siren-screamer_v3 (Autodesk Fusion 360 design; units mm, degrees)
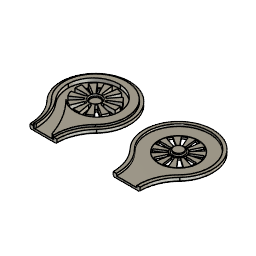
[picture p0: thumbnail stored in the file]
sketch "Skizze1" plane through (0, 0, 0) normal (0, 0, 1) x axis (1, 0, 0)
  line L1 (10, -50) -> (-10, -50)
  line L2 (8.969, -25.7617) -> (10, -50)
  line L3 (14.8492, -14.8492) -> (14.1421, -14.1421)
  line L4 (16.9905, -14.1421) -> (14.1421, -14.1421)
  line L5 (22, 0) -> (20, 0)
  line L6 (16.2635, 16.2635) -> (14.1421, 14.1421)
  line L7 (21.2962, 14.1421) -> (14.1421, 14.1421)
  line L8 (0, 24) -> (0, 20)
  line L9 (-17.6777, 17.6777) -> (-14.1421, 14.1421)
  line L10 (-26, 0) -> (-20, 0)
  line L11 (-19.0919, -19.0919) -> (-14.1421, -14.1421)
  line L12 (0, -10) -> (0, 0)
  line L13 (-21.2132, -21.2132) -> (-19.0919, -19.0919)
  line L14 (-10, -14.1421) -> (-14.1421, -14.1421)
  line L15 (-8, -46.3456) -> (-8, -50)
  circle C1 centre (0, 0) radius 20
  arc A1 centre (1.0544, 0.9401) radius 20.9666 clockwise from (22, 0) to (0, -20)
  arc A2 centre (-0.9455, 1.05) radius 22.9695 clockwise from (0, 24) to (22, 0)
  arc A3 centre (-1.0462, -0.95) radius 24.9719 clockwise from (-26, 0) to (0, 24)
  arc A4 centre (48.368, -48.368) radius 38.4027 clockwise from (10, -50) to (21.2132, -21.2132)
  arc A5 centre (-48.368, -48.368) radius 38.4027 clockwise from (-21.2132, -21.2132) to (-10, -50)
  arc A6 centre (-56.6095, -50) radius 48.6095 clockwise from (-19.0919, -19.0919) to (-8, -50)
  arc A7 centre (0, 0) radius 20 clockwise from (0, -20) to (-14.1421, -14.1421)
  arc A8 centre (4.2758, 0.1591) radius 30.2762 clockwise from (-19.0919, -19.0919) to (-26, 0)
  arc A9 centre (0, 0) radius 30 clockwise from (-21.2132, -21.2132) to (21.2132, -21.2132)
  arc A10 centre (-78.8875, -78.8875) radius 91.5638 clockwise from (-14.1421, -14.1421) to (8, -50)
  point P1 (0, 0)
  point P2 (0, 0)
  point P6 (0, -50)
  point P8 (0, -20)
  point P9 (14.1421, -14.1421)
  point P12 (20, 0)
  point P14 (14.1421, 14.1421)
  point P17 (0, 20)
  point P19 (-14.1421, 14.1421)
  point P21 (-20, 0)
  point P7 (0, 0)
  point P23 (-14.1421, -14.1421)
  point P10 (14.8492, -14.8492)
  point P25 (0, -20)
  point P15 (16.2635, 16.2635)
  point P20 (-17.6777, 17.6777)
  point P29 (0, -20)
  point P33 (0, 0)
  point P4 (10, -50)
  point P37 (-10, -50)
  point P31 (21.2132, -21.2132)
  point P36 (-21.2132, -21.2132)
  point P38 (-8, -50)
  point P40 (-21.2132, -21.2132)
  point P41 (0, 0)
  point P44 (8, -50)
  point P13 (22, 0)
  point P18 (0, 24)
  point P22 (-26, 0)
  point P24 (-19.0919, -19.0919)
  point P3 (-10, -50)
  coincident P1 P2
  horizontal L1
  midpoint L1 P6
  vertical P2 P6
  concentric C1 A9
  coincident C1 P8
  horizontal L4
  coincident C1 P9
  coincident P2 L3
  coincident C1 P12
  horizontal L5
  horizontal L7
  coincident C1 P14
  coincident C1 P17
  vertical L8
  coincident C1 P19
  coincident C1 P21
  horizontal L10
  coincident P7 L10
  coincident P2 L9
  coincident P2 L8
  coincident P1 L6
  coincident P2 L5
  parallel L3 L9
  coincident C1 P23
  coincident P2 L11
  coincident P10 A1
  coincident P8 P25
  coincident P15 A2
  coincident P20 A3
  coincident C1 P29
  coincident P8 P29
  tangent L2 A4
  tangent A4 A9
  coincident P7 P33
  vertical L12
  symmetric P4 L12 P37
  symmetric P31 L12 P36
  symmetric A4 L12 A5
  coincident L1 P38
  coincident A5 P40
  collinear L11 L13
  tangent A6 A8
  vertical P8 P41
  vertical P2 P8
  horizontal L14
  coincident P36 P40
  perpendicular L1 L15
  tangent A6 L15
  tangent C1 A10
  coincident L1 P44
  dimension "d1" diameter A9 = 60
  dimension "d2" diameter C1 = 40
  dimension "d4" distance P9 P10 = 1
  dimension "d5" angle L3 L4 = 45
  dimension "d6" distance P14 P15 = 3
  dimension "d7" angle L6 L7 = 45
  dimension "d8" distance P12 P13 = 2
  dimension "d9" distance P17 P18 = 4
  dimension "d10" distance P19 P20 = 5
  dimension "d11" distance P21 P22 = 6
  dimension "d12" distance P23 P24 = 7
  dimension "d14" distance P3 P4 = 20
  dimension "d15" distance P1 L1 = 50
  dimension "d17" distance P24 P40 = 3
  dimension "d18" distance P3 P38 = 2
  dimension "d20" angle L11 L14 = 45
  dimension "d21" distance P4 P44 = 2
extrude "Extrusion1" new body sketch "Skizze1" profile of A9 L1 A1 A2 A3 A8 A4 A5 A6 A7 A10 against normal blind 1.8 bodies "Frame-in"
sketch "Skizze2" plane through (0, -50, 0) normal (0, -1, 0) x axis (1, 0, 0)
  line L1 (8, 0) -> (10, 0)
  line L2 (10, 0) -> (10, -1.8)
  line L3 (10, -1.8) -> (8, -1.8)
  line L4 (8, -1.8) -> (8, 0)
  line L5 (-10, 0) -> (-8, 0)
  line L6 (-8, 0) -> (-8, -1.8)
  line L7 (-8, -1.8) -> (-10, -1.8)
  line L8 (-10, -1.8) -> (-10, 0)
  line L9 (10.5, -0.9) -> (10, -0.9)
  line L10 (9.7757, -1.8591) -> (9.9, -1.7)
  line L11 (10.157, -1.8393) -> (9.7757, -1.8591)
  circle C1 centre (10.5, -0.9) radius 1
  point P11 (10, -0.9)
  point P10 (10.5, -0.9)
  point P12 (10.5, -0.9)
  point P17 (9.9, -1.7)
  point P19 (10.157, -1.8393)
  point P1 (0, 0)
  midpoint L2 P11
  coincident P10 P12
  horizontal L9
  coincident C1 P17
  coincident C1 P19
  dimension "d24" diameter C1 = 2
  dimension "d25" distance P1 P10 = 10.5
sweep "Sweeping" sketch "Skizze2" TwistAngle 0 TaperAngle 0
sketch "Skizze3" plane through (0, 0, 0) normal (0, 0, 1) x axis (1, 0, 0)
  line L1 (15.9838, 10.2722) -> (6.6774, 4.2913)
  line L2 (19.5, 0) -> (0, 0)
  line L3 (18.2304, 5.3529) -> (0, 0)
  line L4 (18.0324, 5.9859) -> (7.5332, 2.5007)
  circle C1 centre (0, 0) radius 19
  arc A1 centre (7.2181, 3.4499) radius 1.0002 clockwise from (7.5332, 2.5007) to (6.6774, 4.2913)
  circle C2 centre (0, 0) radius 5
  circle C3 centre (0, 0) radius 7
  arc A2 centre (0, 0) radius 18 clockwise from (15.1426, 9.7315) to (17.0834, 5.6708)
  circle C4 centre (0, 0) radius 4.7
  point P1 (0, 0)
  point P2 (0, 0)
  point P3 (0, 0)
  point P6 (0, 0)
  point P4 (15.9838, 10.2722)
  point P7 (18.2304, 5.3529)
  point P8 (18.0324, 5.9859)
  point P12 (0, 0)
  point P15 (17.0834, 5.6708)
  point P14 (15.1426, 9.7315)
  point P13 (0, 0)
  point P16 (0, 0)
  coincident P1 P2
  horizontal L2
  coincident P1 P3
  coincident P1 P6
  coincident C1 P4
  coincident C1 P7
  coincident C1 P8
  tangent L1 A1
  tangent L4 A1
  coincident P1 L4
  coincident P1 P12
  concentric C2 C3
  tangent A1 C3
  coincident L4 P15
  coincident L1 P14
  coincident P13 P16
  concentric C1 C4
  dimension "d34" diameter C1 = 38
  dimension "d36" angle L1 L2 = 32.727 (= "( 360 / d46 ) * 1 deg")
  dimension "d39" angle L3 L4 = 2
  dimension "d40" radius A1 = 1.0002
  dimension "d41" diameter C2 = 10
  dimension "d42" diameter C3 = 14
  dimension "d59" distance P8 P15 = 1
  dimension "d65" diameter C4 = 9.4
extrude "Extrusion2" new body sketch "Skizze3" profile of C1 L1 L4 A1 C2 distance 2 bodies "Rotor"
extrude "Extrusion3" cut sketch "Skizze3" profile of C1 L1 L4 A1 no distance stored
circular_pattern "C-Anordnung1" countU 11 named "d46" TotalAngle 360
work_plane "Arbeitsebene1" AlongDistance -2
sketch "Skizze4" plane through (0, 0, -2) normal (0, 0, 1) x axis (1, 0, 0)
  line L1 (10, -50) -> (-10, -50)
  line L2 (13, -50) -> (10, -50)
  line L3 (13, -54.9842) -> (13, -50)
  line L4 (0, -10) -> (0, 0)
  line L5 (-13, -50) -> (-10, -50)
  circle C1 centre (0, 0) radius 33
  arc A1 centre (52.5, -50) radius 39.5 clockwise from (13, -50) to (23.8966, -22.7586)
  arc A2 centre (0, 0) radius 30 clockwise from (-21.2132, -21.2132) to (21.2132, -21.2132)
  arc A3 centre (-52.5, -50) radius 39.5 clockwise from (-23.8966, -22.7586) to (-13, -50)
  circle C2 centre (0, 0) radius 29
  arc A4 centre (-56.6095, -50) radius 48.6095 clockwise from (-19.0919, -19.0919) to (-8, -50)
  arc A5 centre (-78.8875, -78.8875) radius 91.5638 clockwise from (-14.1421, -14.1421) to (8, -50)
  point P1 (0, 0)
  point P2 (0, 0)
  point P4 (10, -50)
  point P5 (10, -50)
  point P7 (23.8966, -22.7586)
  point P18 (-10, -50)
  point P6 (13, -50)
  point P17 (-13, -50)
  point P16 (-23.8966, -22.7586)
  point P13 (0, 0)
  point P19 (0, 0)
  coincident P1 P2
  coincident P4 P5
  parallel L1 L2
  tangent C1 A1
  coincident C1 P7
  tangent A1 L3
  vertical L3
  symmetric P5 L4 P18
  symmetric P6 L4 P17
  symmetric P7 L4 P16
  symmetric A1 L4 A3
  coincident P13 P19
  dimension "d49" diameter C1 = 66
  dimension "d50" distance P5 P6 = 3
  dimension "d51" distance C1 A2 = 3
  dimension "d52" diameter C2 = 58
extrude "Extrusion4" new body sketch "Skizze4" profile of C1 L1 L2 A1 A3 L5 C2 A4 A5 along normal blind 2 bodies "Frame-out"
combine "Kombinieren1"
extrude "Extrusion5" new body sketch "Skizze4" profile of C1 L1 L2 A1 A3 L5 C2 against normal blind 2 bodies "Frame-out"
extrude "Extrusion7" sketch "Skizze3" profile of C1 L1 L4 A1 C3 A2 blind -0.2
extrude "Extrusion6" cut sketch "Skizze3" profile of L1 L4 A1 A2 to an object
circular_pattern "C-Anordnung2" countU 11 (= "d46") TotalAngle 360
extrude "Extrusion8" sketch "Skizze3" profile of C4 blind 2
fillet "Abrundung1" radius 1
chamfer "Fase1" distance 1
chamfer "Fase2" distance 1
fillet "Abrundung2" radius 1
work_plane "Arbeitsebene2" AlongDistance 40
combine "Kombinieren2" bodies "Frame-out"
mirror "Spiegeln2" mirrorStitchTolerance 0.1
extrude "Extrusion9" cut of existing geometry blind -0.2
mirror "Spiegeln3" mirrorStitchTolerance 0.1 bodies "Frame-out (1)"
named bodies: "Frame-in", "Rotor", "Frame-out", "Frame-out (1)"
